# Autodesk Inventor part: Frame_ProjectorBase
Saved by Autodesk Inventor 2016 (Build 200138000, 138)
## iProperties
Created: 2015-11
Part Number: Frame_ProjectorBase
Material: Generic
Document SubType Name: Modeling
Designer: John
Density: 1 g/cm^3
Appearance: Default
Author: John
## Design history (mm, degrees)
feature "SOLID1"
body "Solid1"
